(* Logix 5000 project; controller SinglePumpTest 1769-L16ER-BB1B rev 30.11; software revision 30.00 *)

TASK MainTask (continuous, watchdog 500 ms) : MainProgram

MODULES
   Local : 1769-L16ER-BB1B (PointIO 0, rev 30.11)
      VMP_01 : ETHERNET-MODULE (Ethernet 192.168.1.151, rev 1.1, Output RPI 200 ms)   // Pump 01
           VMP_01:O.Data[1]   // Start In
           VMP_01:O.Data[3]   // Continuous Run
           VMP_01:O.Data[5]   // Next Program
           VMP_01:O.Data[7]   // Loop Delay
           VMP_01:O.Data[9]   // Direction
           VMP_01:O.Data[10]   // Initial RPM
           VMP_01:O.Data[20]   // Spare[7]
           VMP_01:O.Data[12]   // Final RPM
           VMP_01:O.Data[22]   // Spare Real[0]
           VMP_01:O.Data[14]   // Spare[1]
           VMP_01:O.Data[24]   // Spare Real[2]
           VMP_01:O.Data[16]   // Spare[3]
           VMP_01:O.Data[18]   // Spare[5]
           VMP_01:O.Data[0]   // Ready In
           VMP_01:O.Data[2]   // Abort Run
           VMP_01:O.Data[4]   // Current Program
           VMP_01:O.Data[6]   // Loop Cycles
           VMP_01:O.Data[8]   // Pull Back
           VMP_01:O.Data[11]   // RPM
           VMP_01:O.Data[21]   // Volume
           VMP_01:O.Data[13]   // Spare[0]
           VMP_01:O.Data[23]   // Spare Real[1]
           VMP_01:O.Data[15]   // Spare[2]
           VMP_01:O.Data[25]   // Spare Real[3]
           VMP_01:O.Data[17]   // Spare[4]
           VMP_01:O.Data[19]   // Spare[6]
           VMP_01:C.Data[0]   // Bore[0]
           VMP_01:C.Data[1]   // Bore[1]
           VMP_01:C.Data[2]   // Bore[2]
           VMP_01:C.Data[3]   // Bore[3]
           VMP_01:C.Data[4]   // Bore[4]
           VMP_01:C.Data[5]   // Bore[5]
           VMP_01:C.Data[6]   // Bore[6]
           VMP_01:C.Data[7]   // Bore[7]
           VMP_01:C.Data[8]   // Bore[8]
           VMP_01:C.Data[9]   // Bore[9]
           VMP_01:C.Data[10]   // Bore[10]
           VMP_01:C.Data[11]   // Bore[11]
           VMP_01:C.Data[12]   // Spare1[0]
           VMP_01:C.Data[13]   // Spare1[1]
           VMP_01:C.Data[14]   // Spare1[2]
           VMP_01:C.Data[15]   // Spare1[3]
           VMP_01:C.Data[16]   // Spare1[4]
           VMP_01:C.Data[17]   // Spare1[5]
           VMP_01:C.Data[18]   // Spare1[6]
           VMP_01:C.Data[19]   // Spare1[7]
           VMP_01:C.Data[20]   // Hold On Fault
           VMP_01:C.Data[21]   // Units
           VMP_01:C.Data[22]   // EthernNet Run Ready
           VMP_01:C.Data[23]   // Ready Inter Lock
           VMP_01:C.Data[24]   // Spare2[0]
           VMP_01:C.Data[25]   // Spare2[1]
           VMP_01:C.Data[26]   // Spare2[2]
           VMP_01:C.Data[27]   // Spare2[3]
           VMP_01:C.Data[28]   // Spare2[4]
           VMP_01:C.Data[29]   // Spare2[5]
           VMP_01:C.Data[30]   // Spare2[6]
           VMP_01:C.Data[31]   // Spare2[7]
           VMP_01:I.Data[1]   // Busy
           VMP_01:I.Data[3]   // Direction
           VMP_01:I.Data[5]   // Pump Number
           VMP_01:I.Data[7]   // Next Program
           VMP_01:I.Data[9]   // Fault
           VMP_01:I.Data[10]   // Spare[0]
           VMP_01:I.Data[20]   // Spare[10]
           VMP_01:I.Data[30]   // Spare Float[5]
           VMP_01:I.Data[12]   // Spare[2]
           VMP_01:I.Data[22]   // Shot Size
           VMP_01:I.Data[32]   // Spare Float[7]
           VMP_01:I.Data[14]   // Spare[4]
           VMP_01:I.Data[24]   // Total
           VMP_01:I.Data[16]   // Spare[6]
           VMP_01:I.Data[26]   // Spare Float[1]
           VMP_01:I.Data[18]   // Spare[8]
           VMP_01:I.Data[28]   // Spare Float[3]
           VMP_01:I.Data[0]   // Ready
           VMP_01:I.Data[2]   // Motor Enabled
           VMP_01:I.Data[4]   // Current Revolution
           VMP_01:I.Data[6]   // Current Program
           VMP_01:I.Data[8]   // Approx Time
           VMP_01:I.Data[11]   // Spare[1]
           VMP_01:I.Data[21]   // Spare[11]
           VMP_01:I.Data[31]   // Spare Float[6]
           VMP_01:I.Data[13]   // Spare[3]
           VMP_01:I.Data[23]   // Current Volume
           VMP_01:I.Data[33]   // Spare Float[8]
           VMP_01:I.Data[15]   // Spare[5]
           VMP_01:I.Data[25]   // Spare Float[0]
           VMP_01:I.Data[17]   // Spare[7]
           VMP_01:I.Data[27]   // Spare Float[2]
           VMP_01:I.Data[19]   // Spare[9]
           VMP_01:I.Data[29]   // Spare Float[4]
      Pump01 : vendor 1449 type 36 code 17 (Ethernet 192.168.168.122, rev 1.1, StandardDataDriven RPI 20 ms)
           Pump01:I.Data[0]   // vmpStatus
           Pump01:I.Data[1]   // vmpFaults
           Pump01:I.Data[2]   // spare
           Pump01:I.Data[3]   // currentRevolution
           Pump01:I.Data[4]   // currentProgram
           Pump01:I.Data[5]   // approxTime
           Pump01:I.Data[6]   // spareDInt0
           Pump01:I.Data[7]   // spareDInt1
           Pump01:I.Data[8]   // spareDInt2
           Pump01:I.Data[9]   // SpareDint3
           Pump01:I.Data[10]   // shotSize
           Pump01:I.Data[11]   // currentVolumn
           Pump01:I.Data[12]   // total
           Pump01:I.Data[13]   // SpareReal0
           Pump01:I.Data[14]   // SpareReal1
           Pump01:I.Data[15]   // SpareReal2
           Pump01:I.Data[16]   // SpareReal3
           Pump01:I.Data[0].0   // vmpStatus_Ready
           Pump01:I.Data[0].2   // vmpStatus_Abort
           Pump01:I.Data[0].3   // vmpStatus_Direction
           Pump01:I.Data[0].4   // vmpStatus_ContinuousRun
           Pump01:I.Data[0].5   // vmpStatus_MotorRunning
           Pump01:I.Data[0].1   // vmpStatus_Running
           Pump01:O.Data[0]   // plcCmd
           Pump01:O.Data[0].0   // plcCmd_Ready
           Pump01:O.Data[0].1   // plcCmd_Start
           Pump01:O.Data[0].2   // plcCmd_Abort
           Pump01:O.Data[0].3   // plcCmd_Direction
           Pump01:O.Data[0].4   // plcCmd_ContinuousRun
           Pump01:O.Data[0].5   // plcCmd_SetMaxShotSize
           Pump01:O.Data[1]   // Spare
           Pump01:O.Data[2]   // currentProgram
           Pump01:O.Data[3]   // revolutions
           Pump01:O.Data[4]   // SpareDint0
           Pump01:O.Data[5]   // SpareDint1
           Pump01:O.Data[6]   // SpareDint2
           Pump01:O.Data[7]   // SpareDint3
           Pump01:O.Data[8]   // volume
           Pump01:O.Data[9]   // SpareReal0
           Pump01:O.Data[10]   // SpareReal1
           Pump01:O.Data[11]   // SpareReal2
           Pump01:O.Data[12]   // SpareReal3
           Pump01:O.Data[0].6   // plcCmd_SetShotSize
           Pump01:O.Data[0].7   // plcCmd_IgnoreCmds
      Discrete_IO : Embedded (PointIO 1, rev 30.11, Output RPI 20 ms)
           Local:1:O.Data.1   // Red Light
END_MODULES

TYPE VMP_Input :   // Data received from the Pump
STRUCT
   vmpStatus : DINT;   // Bits indicating the status
   vmpStatus_Ready : BOOL;   // Pump is ready to run
   vmpStatus_Running : BOOL;   // Pump is running.
   vmpStatus_Abort : BOOL;   // Pump is in an Abort state
   vmpStatus_Direction : BOOL;   // Turning counter clockwise
   vmpStatus_ContinuousRun : BOOL;   // In continuous run mode
   vmpStatus_MotorRunning : BOOL;   // One of the motors is running
   vmpFaults : DINT;   // Faults as a bit mask
   vmpFaults_DispenseMotor : BOOL;   // Dispense Motor
   vmpFaults_AdjustMotor : BOOL;   // Adjustmemt Motor
   SpareBits : DINT;   // Spara Data bits
   currentProgram : DINT;   // Current selected program
   revolutions : DINT;   // Number of revolutions
   SpareDInt1 : DINT;   // Spare data
   SpareDInt2 : DINT;   // Spare data
   SpareDInt3 : DINT;   // Spare data
   SpareDInt4 : DINT;   // Spare data
   volume : REAL;   // Current volume
   SpareReal1 : REAL;   // Spare data
   SpareReal2 : REAL;   // Spare data
   SpareReal3 : REAL;   // Spare data
   SpareReal4 : REAL;   // Spare data
END_STRUCT
END_TYPE

TYPE VMP_Output :   // Data sent to the pump
STRUCT
   plcCmd : DINT;   // Pump commands as bit fields
   plcCmd_Ready : BOOL;   // Ok to run pump
   plcCmd_Start : BOOL;   // Start the pump
   plcCmd_Abort : BOOL;   // Abort Running program
   plcCmd_Direction : BOOL;   // Turning counter clockwise
   plcCmd_ContinuousRun : BOOL;   // Run continuously
   plcCmd_SetMaxShotSize : BOOL;   // Set volume to max size
   Spare : DINT;   // Spare bits
   currentProgram : DINT;   // Proram number to run
   revolutions : DINT;   // Number of revolutions to turn
   Spare_1 : DINT;   // Spare data
   Spare_2 : DINT;   // Spare data
   Spare_3 : DINT;   // Spare data
   Spare_4 : DINT;   // Spare data
   volume : REAL;   // Set volume size
   SpareReal_1 : REAL;   // Spare data
   SpareReal_2 : REAL;   // Spare data
   SpareReal_3 : REAL;   // Spare data
   SpareReal_4 : REAL;   // Spare data
END_STRUCT
END_TYPE

TYPE VMP_Program :   // Program Parameters
STRUCT
   Current_Program : DINT;   // Currently Selected Program
   Direction : DINT;   // Rotational direction of the pump motor.
   Pull_Back : DINT;   // Percentage rotation to reverse the pump after a shot. E.g. suck back.
   Initial_RPM : DINT;   // Initial speed of the pump.
   RPM : DINT;   // Speed of the pump after initial RPM
   Final_RPM : DINT;   // Final speed of the pump after RPM.
   Fine_Adjust : DINT;   // 1=Increment, 0=Clear, -1=Decrement fine adjust.
   Set_Shot : DINT;   // Reset size to zero then to current program setting.
   Acceleration : DINT;   // Set speed of acceleration for initial RPM.
   Deceleration : DINT;   // Set speed of deceleration for final RPM.
   Loop_Cycles : DINT;   // Number of times to run the linked program.
   Linked_Program : DINT;   // -1=Disabled, 0 to 49 next program to run.
   Linked_Time_Delay : DINT;   // Number of seconds to wait before running the linked program.
   Motor_Current : DINT;   // Percentage current used to drive the motor.
   Continuous_Run : DINT;   // 0=Normal Mode, 1=Continuous Run Mode
   Revolutions : DINT;   // Number of revolutions to turn the pump head.
   Approx_Time : DINT;   // Approximate time in mill-seconds for a dispense time.
   Volume : REAL;   // Shot Volume
   Program_Name : STRING;   // Name of the current program.
END_STRUCT
END_TYPE

VAR_GLOBAL   (* controller tags *)
   Green_Light_On : ALIAS FOR Local:1:O.Data.0;
   Run_Pump : BOOL;
   Run_Pump_In : ALIAS FOR Run_Pump;
   Run_Pump_In_2 : ALIAS FOR Stop_Btn;
   Start_Btn : ALIAS FOR Local:1:I.Data.0;
   Stop_Btn : ALIAS FOR Local:1:I.Data.1;
   T1 : TIMER := (PRE := 1000);   // Cycle Timer
   VMP_01_Start : ALIAS FOR VMP_01:O.Data[1].0;
END_VAR

PROGRAM MainProgram   (* main routine MainRoutine *)

ROUTINE MainRoutine   (* ladder *)
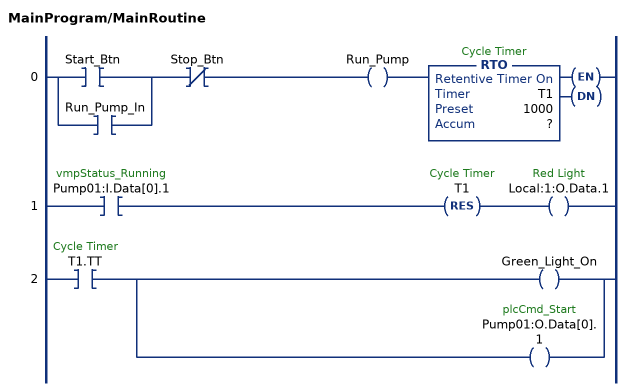
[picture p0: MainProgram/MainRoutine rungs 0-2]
   0: [XIC(Start_Btn) ,XIC(Run_Pump_In) ]XIO(Stop_Btn)OTE(Run_Pump)RTO(T1,?,?);
   1: XIC(Pump01:I.Data[0].1)RES(T1)OTE(Local:1:O.Data.1);
   2: XIC(T1.TT)[OTE(Green_Light_On) ,OTE(Pump01:O.Data[0].1) ];
END_ROUTINE
END_PROGRAM
